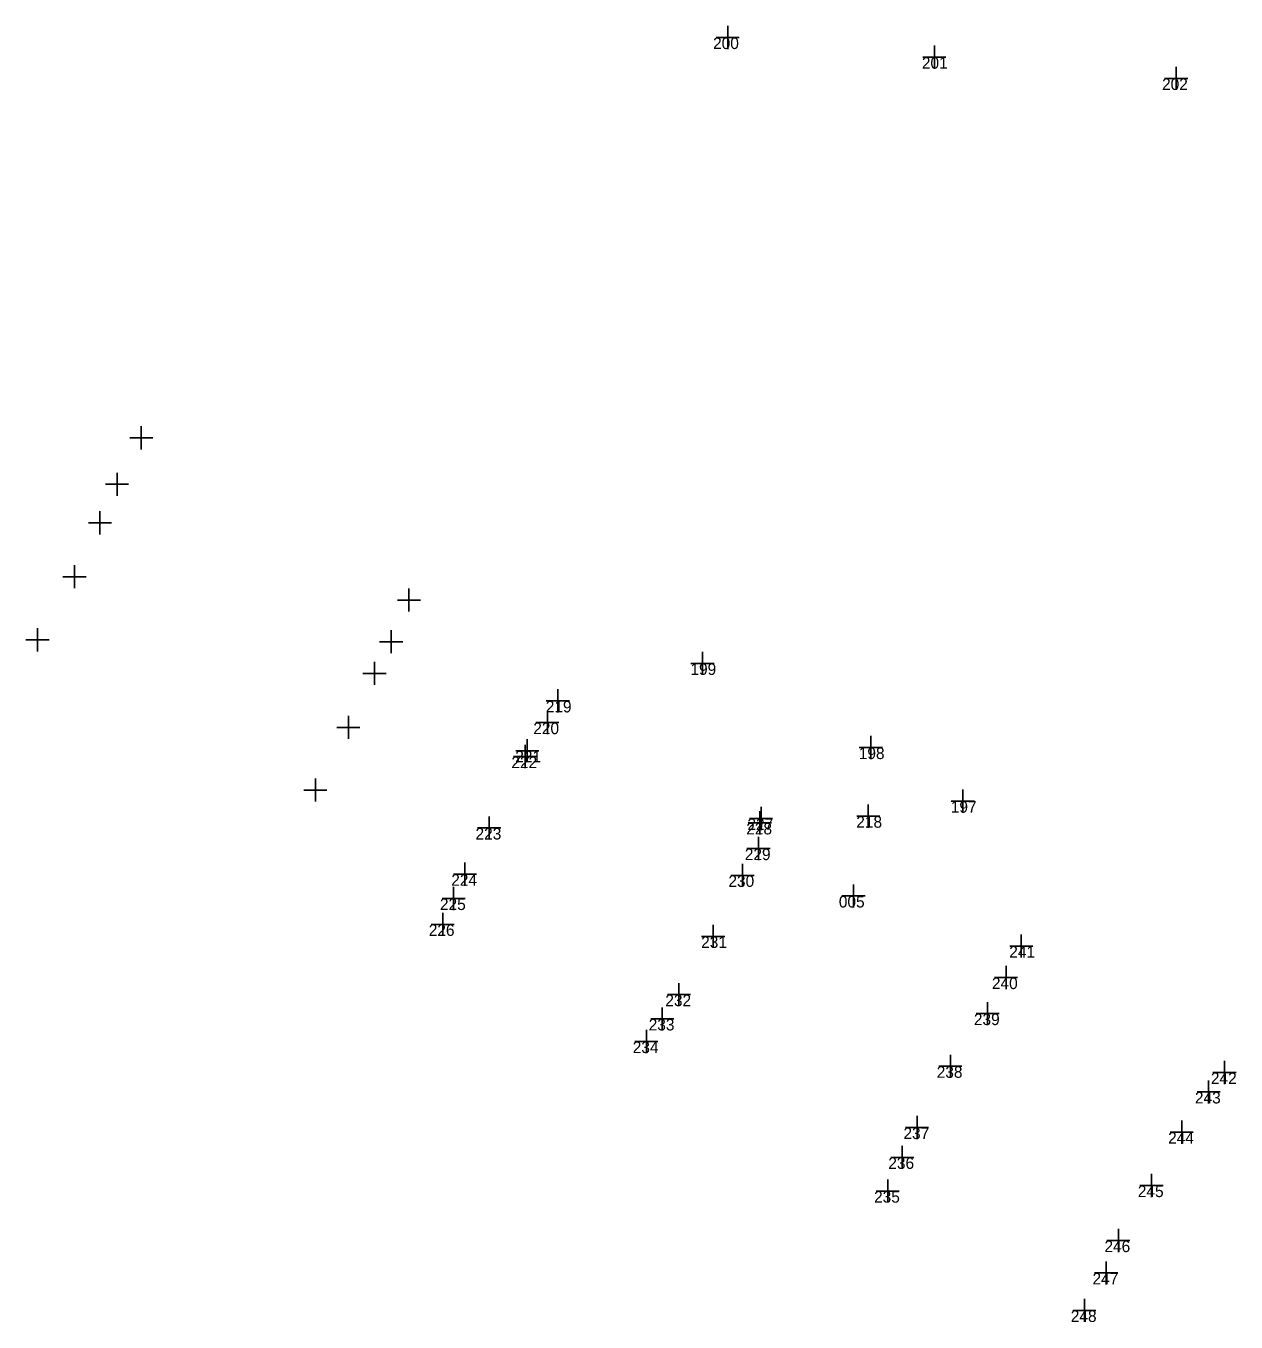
# Model space of a CAD drawing. Extents: x -706655 to -706193, y -1036183 to -1034979.
# Drawn here: x -706294.5 to -706242.2, y -1036182.5 to -1036126.4 of the extents above; entities that cross this region are included whole.
import ezdxf

# ---------------------------------------------------------------- set-up
doc = ezdxf.new("R2010")
doc.units = 0
doc.layers.add('čísla bodu', color=7, linetype='Continuous')

msp = doc.modelspace()

# ---------------------------------------------------------------- linework, layer by layer
at = {"layer": 'čísla bodu'}
for p, q in [((-706264.14, -1036127.43), (-706264.14, -1036126.43)), ((-706264.64, -1036126.93), (-706263.64, -1036126.93)), ((-706264.14, -1036126.93), (-706264.14, -1036126.93)), ((-706255.2, -1036128.28), (-706255.2, -1036127.28)), ((-706255.7, -1036127.78), (-706254.7, -1036127.78)), ((-706255.2, -1036127.78), (-706255.2, -1036127.78)), ((-706244.74, -1036129.2), (-706244.74, -1036128.2)), ((-706245.24, -1036128.7), (-706244.24, -1036128.7)), ((-706244.74, -1036128.7), (-706244.74, -1036128.7)), ((-706289.51, -1036144.75), (-706289.51, -1036143.75)), ((-706289.51, -1036144.75), (-706289.51, -1036143.75)), ((-706290.01, -1036144.25), (-706289.01, -1036144.25)), ((-706290.01, -1036144.25), (-706289.01, -1036144.25)), ((-706289.51, -1036144.25), (-706289.51, -1036144.25)), ((-706289.51, -1036144.25), (-706289.51, -1036144.25)), ((-706290.56, -1036146.76), (-706290.56, -1036145.76)), ((-706290.56, -1036146.76), (-706290.56, -1036145.76)), ((-706291.06, -1036146.26), (-706290.06, -1036146.26)), ((-706291.06, -1036146.26), (-706290.06, -1036146.26)), ((-706290.56, -1036146.26), (-706290.56, -1036146.26)), ((-706290.56, -1036146.26), (-706290.56, -1036146.26)), ((-706291.3, -1036148.43), (-706291.3, -1036147.43)), ((-706291.3, -1036148.43), (-706291.3, -1036147.43)), ((-706291.8, -1036147.93), (-706290.8, -1036147.93)), ((-706291.8, -1036147.93), (-706290.8, -1036147.93)), ((-706291.3, -1036147.93), (-706291.3, -1036147.93)), ((-706291.3, -1036147.93), (-706291.3, -1036147.93)), ((-706292.4, -1036150.76), (-706292.4, -1036149.76)), ((-706292.4, -1036150.76), (-706292.4, -1036149.76)), ((-706292.9, -1036150.26), (-706291.9, -1036150.26)), ((-706292.9, -1036150.26), (-706291.9, -1036150.26)), ((-706292.4, -1036150.26), (-706292.4, -1036150.26)), ((-706292.4, -1036150.26), (-706292.4, -1036150.26)), ((-706277.93, -1036151.77), (-706277.93, -1036150.77)), ((-706277.93, -1036151.77), (-706277.93, -1036150.77)), ((-706278.43, -1036151.27), (-706277.43, -1036151.27)), ((-706278.43, -1036151.27), (-706277.43, -1036151.27)), ((-706277.93, -1036151.27), (-706277.93, -1036151.27)), ((-706277.93, -1036151.27), (-706277.93, -1036151.27)), ((-706294, -1036153.49), (-706294, -1036152.49)), ((-706294, -1036153.49), (-706294, -1036152.49)), ((-706278.7, -1036153.57), (-706278.7, -1036152.57)), ((-706278.7, -1036153.57), (-706278.7, -1036152.57)), ((-706294.5, -1036152.99), (-706293.5, -1036152.99)), ((-706294.5, -1036152.99), (-706293.5, -1036152.99)), ((-706294, -1036152.99), (-706294, -1036152.99)), ((-706294, -1036152.99), (-706294, -1036152.99)), ((-706279.2, -1036153.07), (-706278.2, -1036153.07)), ((-706279.2, -1036153.07), (-706278.2, -1036153.07)), ((-706278.7, -1036153.07), (-706278.7, -1036153.07)), ((-706278.7, -1036153.07), (-706278.7, -1036153.07)), ((-706265.23, -1036154.51), (-706265.23, -1036153.51)), ((-706279.92, -1036154.44), (-706278.92, -1036154.44)), ((-706279.92, -1036154.44), (-706278.92, -1036154.44)), ((-706279.42, -1036154.94), (-706279.42, -1036153.94)), ((-706279.42, -1036154.94), (-706279.42, -1036153.94)), ((-706279.42, -1036154.44), (-706279.42, -1036154.44)), ((-706279.42, -1036154.44), (-706279.42, -1036154.44)), ((-706265.73, -1036154.01), (-706264.73, -1036154.01)), ((-706265.23, -1036154.01), (-706265.23, -1036154.01)), ((-706271.49, -1036156.13), (-706271.49, -1036155.13)), ((-706271.99, -1036155.63), (-706270.99, -1036155.63)), ((-706271.94, -1036157.07), (-706271.94, -1036156.07)), ((-706271.49, -1036155.63), (-706271.49, -1036155.63)), ((-706280.55, -1036157.28), (-706280.55, -1036156.28)), ((-706280.55, -1036157.28), (-706280.55, -1036156.28)), ((-706272.44, -1036156.57), (-706271.44, -1036156.57)), ((-706271.94, -1036156.57), (-706271.94, -1036156.57)), ((-706281.05, -1036156.78), (-706280.05, -1036156.78)), ((-706281.05, -1036156.78), (-706280.05, -1036156.78)), ((-706280.55, -1036156.78), (-706280.55, -1036156.78)), ((-706280.55, -1036156.78), (-706280.55, -1036156.78)), ((-706257.95, -1036158.15), (-706257.95, -1036157.15)), ((-706273.31, -1036157.79), (-706272.31, -1036157.79)), ((-706272.91, -1036158.54), (-706272.91, -1036157.54)), ((-706272.81, -1036158.29), (-706272.81, -1036157.29)), ((-706272.81, -1036157.79), (-706272.81, -1036157.79)), ((-706258.45, -1036157.65), (-706257.45, -1036157.65)), ((-706257.95, -1036157.65), (-706257.95, -1036157.65)), ((-706273.41, -1036158.04), (-706272.41, -1036158.04)), ((-706272.91, -1036158.04), (-706272.91, -1036158.04)), ((-706282.48, -1036159.49), (-706281.48, -1036159.49)), ((-706282.48, -1036159.49), (-706281.48, -1036159.49)), ((-706281.98, -1036159.99), (-706281.98, -1036158.99)), ((-706281.98, -1036159.99), (-706281.98, -1036158.99)), ((-706281.98, -1036159.49), (-706281.98, -1036159.49)), ((-706281.98, -1036159.49), (-706281.98, -1036159.49)), ((-706253.97, -1036160.47), (-706253.97, -1036159.47)), ((-706254.47, -1036159.97), (-706253.47, -1036159.97)), ((-706253.97, -1036159.97), (-706253.97, -1036159.97)), ((-706274.46, -1036161.63), (-706274.46, -1036160.63)), ((-706262.75, -1036161.41), (-706262.75, -1036160.41)), ((-706262.7, -1036161.22), (-706262.7, -1036160.22)), ((-706258.56, -1036160.62), (-706257.56, -1036160.62)), ((-706258.06, -1036161.12), (-706258.06, -1036160.12)), ((-706258.06, -1036160.62), (-706258.06, -1036160.62)), ((-706274.96, -1036161.13), (-706273.96, -1036161.13)), ((-706274.46, -1036161.13), (-706274.46, -1036161.13)), ((-706263.25, -1036160.91), (-706262.25, -1036160.91)), ((-706263.2, -1036160.72), (-706262.2, -1036160.72)), ((-706262.75, -1036160.91), (-706262.75, -1036160.91)), ((-706262.7, -1036160.72), (-706262.7, -1036160.72)), ((-706262.81, -1036162.52), (-706262.81, -1036161.52)), ((-706263.31, -1036162.02), (-706262.31, -1036162.02)), ((-706262.81, -1036162.02), (-706262.81, -1036162.02)), ((-706275.51, -1036163.63), (-706275.51, -1036162.63)), ((-706263.5, -1036163.68), (-706263.5, -1036162.68)), ((-706276.01, -1036163.13), (-706275.01, -1036163.13)), ((-706275.51, -1036163.13), (-706275.51, -1036163.13)), ((-706264, -1036163.18), (-706263, -1036163.18)), ((-706263.5, -1036163.18), (-706263.5, -1036163.18)), ((-706276, -1036164.68), (-706276, -1036163.68)), ((-706258.7, -1036164.57), (-706258.7, -1036163.57)), ((-706276.5, -1036164.18), (-706275.5, -1036164.18)), ((-706276, -1036164.18), (-706276, -1036164.18)), ((-706259.2, -1036164.07), (-706258.2, -1036164.07)), ((-706258.7, -1036164.07), (-706258.7, -1036164.07)), ((-706276.47, -1036165.8), (-706276.47, -1036164.8)), ((-706276.97, -1036165.3), (-706275.97, -1036165.3)), ((-706276.47, -1036165.3), (-706276.47, -1036165.3)), ((-706264.77, -1036166.32), (-706264.77, -1036165.32)), ((-706265.27, -1036165.82), (-706264.27, -1036165.82)), ((-706264.77, -1036165.82), (-706264.77, -1036165.82)), ((-706251.94, -1036166.24), (-706250.94, -1036166.24)), ((-706251.44, -1036166.74), (-706251.44, -1036165.74)), ((-706251.44, -1036166.24), (-706251.44, -1036166.24)), ((-706252.1, -1036168.1), (-706252.1, -1036167.1)), ((-706266.25, -1036168.84), (-706266.25, -1036167.84)), ((-706252.6, -1036167.6), (-706251.6, -1036167.6)), ((-706252.1, -1036167.6), (-706252.1, -1036167.6)), ((-706266.75, -1036168.34), (-706265.75, -1036168.34)), ((-706266.25, -1036168.34), (-706266.25, -1036168.34)), ((-706266.97, -1036169.89), (-706266.97, -1036168.89)), ((-706252.9, -1036169.66), (-706252.9, -1036168.66)), ((-706267.47, -1036169.39), (-706266.47, -1036169.39)), ((-706266.97, -1036169.39), (-706266.97, -1036169.39)), ((-706253.4, -1036169.16), (-706252.4, -1036169.16)), ((-706252.9, -1036169.16), (-706252.9, -1036169.16)), ((-706267.66, -1036170.87), (-706267.66, -1036169.87)), ((-706268.16, -1036170.37), (-706267.16, -1036170.37)), ((-706267.66, -1036170.37), (-706267.66, -1036170.37)), ((-706254.51, -1036171.94), (-706254.51, -1036170.94)), ((-706242.65, -1036172.21), (-706242.65, -1036171.21)), ((-706255.01, -1036171.44), (-706254.01, -1036171.44)), ((-706254.51, -1036171.44), (-706254.51, -1036171.44)), ((-706243.15, -1036171.71), (-706242.15, -1036171.71)), ((-706242.65, -1036171.71), (-706242.65, -1036171.71)), ((-706243.34, -1036173.05), (-706243.34, -1036172.05)), ((-706243.84, -1036172.55), (-706242.84, -1036172.55)), ((-706243.34, -1036172.55), (-706243.34, -1036172.55)), ((-706256.45, -1036174.09), (-706255.45, -1036174.09)), ((-706255.95, -1036174.59), (-706255.95, -1036173.59)), ((-706255.95, -1036174.09), (-706255.95, -1036174.09)), ((-706244.5, -1036174.79), (-706244.5, -1036173.79)), ((-706245, -1036174.29), (-706244, -1036174.29)), ((-706244.5, -1036174.29), (-706244.5, -1036174.29)), ((-706256.59, -1036175.88), (-706256.59, -1036174.88)), ((-706257.09, -1036175.38), (-706256.09, -1036175.38)), ((-706256.59, -1036175.38), (-706256.59, -1036175.38)), ((-706245.81, -1036177.1), (-706245.81, -1036176.1)), ((-706257.72, -1036176.84), (-706256.72, -1036176.84)), ((-706257.22, -1036177.34), (-706257.22, -1036176.34)), ((-706257.22, -1036176.84), (-706257.22, -1036176.84)), ((-706246.31, -1036176.6), (-706245.31, -1036176.6)), ((-706245.81, -1036176.6), (-706245.81, -1036176.6)), ((-706247.24, -1036179.48), (-706247.24, -1036178.48)), ((-706247.74, -1036178.98), (-706246.74, -1036178.98)), ((-706247.24, -1036178.98), (-706247.24, -1036178.98)), ((-706247.77, -1036180.88), (-706247.77, -1036179.88)), ((-706248.27, -1036180.38), (-706247.27, -1036180.38)), ((-706247.77, -1036180.38), (-706247.77, -1036180.38)), ((-706248.71, -1036182.5), (-706248.71, -1036181.5)), ((-706249.21, -1036182), (-706248.21, -1036182)), ((-706248.71, -1036182), (-706248.71, -1036182))]:
    msp.add_line(p, q, dxfattribs=at)

# ---------------------------------------------------------------- texts
for s, p in [('200', (-706264.774, -1036127.43)), ('201', (-706255.742, -1036128.28)), ('202', (-706245.352, -1036129.2)), ('199', (-706265.754, -1036154.51)), ('219', (-706272.012, -1036156.13)), ('220', (-706272.552, -1036157.07)), ('221', (-706273.331, -1036158.29)), ('198', (-706258.472, -1036158.15)), ('222', (-706273.5, -1036158.54)), ('197', (-706254.492, -1036160.47)), ('218', (-706258.58, -1036161.12)), ('223', (-706275.05, -1036161.63)), ('228', (-706263.34, -1036161.41)), ('227', (-706263.29, -1036161.22)), ('229', (-706263.402, -1036162.52)), ('224', (-706276.1, -1036163.63)), ('230', (-706264.112, -1036163.68)), ('225', (-706276.59, -1036164.68)), ('005', (-706259.334, -1036164.57)), ('226', (-706277.074, -1036165.8)), ('231', (-706265.291, -1036166.32)), ('241', (-706251.961, -1036166.74)), ('240', (-706252.712, -1036168.1)), ('232', (-706266.84, -1036168.84)), ('233', (-706267.56, -1036169.89)), ('239', (-706253.492, -1036169.66)), ('234', (-706268.25, -1036170.87)), ('238', (-706255.1, -1036171.94)), ('242', (-706243.24, -1036172.21)), ('243', (-706243.93, -1036173.05)), ('237', (-706256.54, -1036174.59)), ('244', (-706245.09, -1036174.79)), ('236', (-706257.194, -1036175.88)), ('235', (-706257.81, -1036177.34)), ('245', (-706246.4, -1036177.1)), ('246', (-706247.844, -1036179.48)), ('247', (-706248.36, -1036180.88)), ('248', (-706249.3, -1036182.5))]:
    msp.add_text(s, height=0.5, dxfattribs=at).set_placement(p)

doc.saveas('drawing.dxf')
